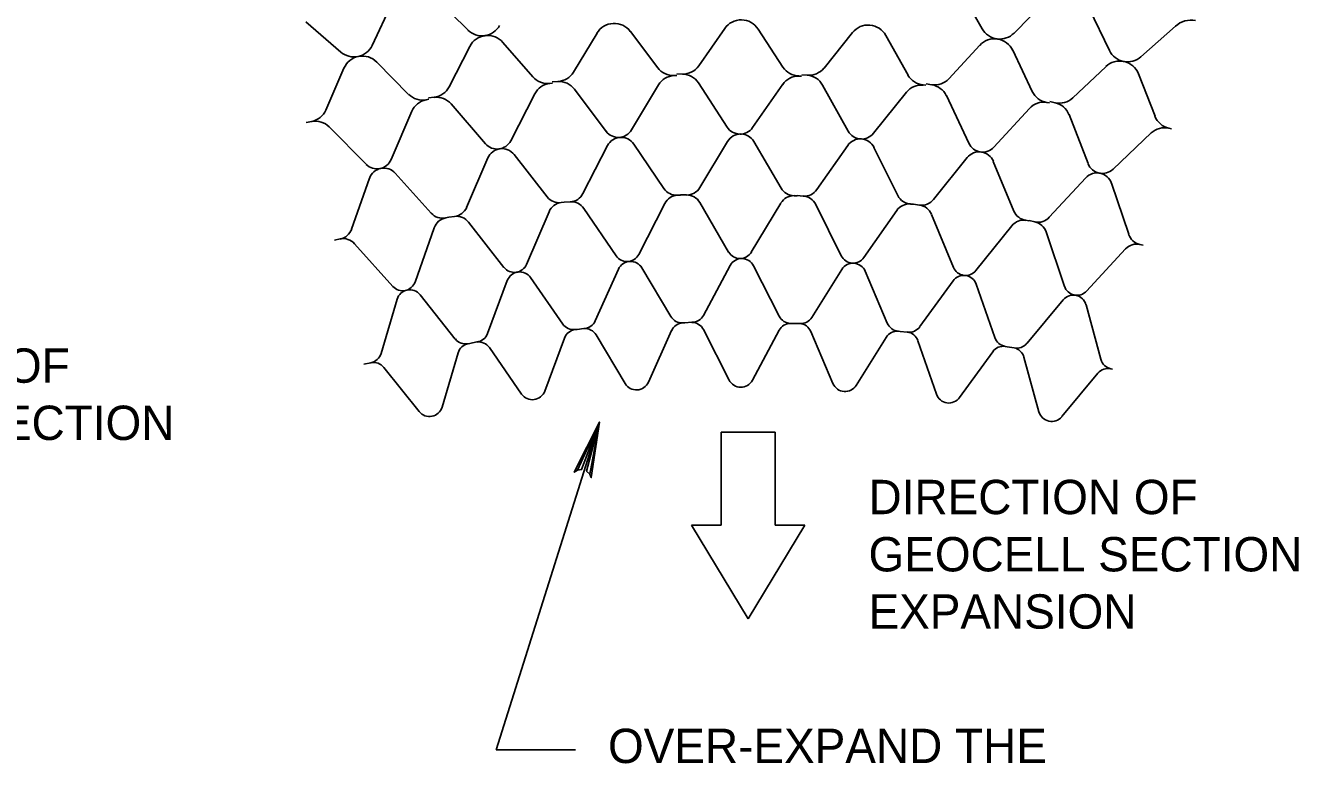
# Model space of a CAD drawing. Extents: x 638850 to 644908, y 297188 to 298900.
# Drawn here: x 639929 to 640040.3, y 297587.2 to 297651.7 of the extents above; entities that cross this region are included whole.
import ezdxf

# ---------------------------------------------------------------- set-up
doc = ezdxf.new("R2010")
doc.units = 0
for name, color, linetype in [('1', 7, 'Continuous'), ('5', 7, 'Continuous'), ('50', 7, 'Continuous'), ('9', 7, 'Continuous')]:
    doc.layers.add(name, color=color, linetype=linetype)

msp = doc.modelspace()

# ---------------------------------------------------------------- linework, layer by layer
at = {"layer": '1'}
for p, q in [((639970.17, 297588.39), (639979.19, 297617.04)), ((639994.53, 297616.16), (639989.82, 297616.16)), ((639989.82, 297616.16), (639989.82, 297608.04)), ((639994.53, 297608.04), (639994.53, 297616.16)), ((639989.82, 297608.04), (639987.22, 297608.04)), ((639987.22, 297608.04), (639992.17, 297599.84)), ((639992.17, 297599.84), (639997.13, 297608.04)), ((639997.13, 297608.04), (639994.53, 297608.04))]:
    msp.add_line(p, q, dxfattribs=at)
msp.add_lwpolyline([(639977.26, 297612.82), (639977.63, 297612.88), (639979.19, 297617.04), (639977.26, 297612.82), (639976.99, 297612.65), (639979.19, 297617.04), (639978.07, 297612.75), (639978.34, 297612.49), (639979.19, 297617.04), (639978.47, 297612.19), (639978.34, 297612.49)], dxfattribs=at)
at = {"layer": '5'}
for p, q in [((640010.63, 297654.9), (640012.63, 297651.38)), ((639964.82, 297654.14), (639967.69, 297651.29)), ((640015.42, 297651.01), (640018.26, 297653.89)), ((639959.33, 297649.94), (639961.05, 297653.61)), ((640021.98, 297653.15), (640023.74, 297649.5)), ((639953.53, 297652.01), (639956.59, 297649.36)), ((640026.49, 297648.94), (640029.53, 297651.63)), ((639976.93, 297647.6), (639978.98, 297651.01)), ((639981.89, 297651.16), (639984.28, 297647.98)), ((639987.86, 297648.15), (639990.14, 297651.41)), ((639993.06, 297651.37), (639995.22, 297648.03)), ((639998.81, 297647.96), (640001.3, 297651.06)), ((640004.21, 297650.81), (640006.15, 297647.34)), ((639966.05, 297646.31), (639967.87, 297649.85)), ((639970.76, 297650.2), (639973.36, 297647.19)), ((640009.72, 297647.03), (640012.42, 297649.95)), ((640015.3, 297649.51), (640017, 297645.91)), ((639959.73, 297648.48), (639962.52, 297645.66)), ((639955.29, 297644.29), (639956.86, 297647.94)), ((639985.72, 297647.31), (639985.95, 297647.32)), ((639985.95, 297647.44), (639986.45, 297647.43)), ((639996.61, 297647.26), (639996.85, 297647.26)), ((639996.86, 297647.38), (639997.35, 297647.34)), ((640020.54, 297645.35), (640023.43, 297648.08)), ((640026.28, 297647.45), (640027.73, 297643.75)), ((639974.84, 297646.62), (639975.08, 297646.64)), ((639975.07, 297646.76), (639975.56, 297646.79)), ((639977, 297646.11), (639979.77, 297642.43)), ((639981.98, 297642.55), (639984.35, 297646.49)), ((639987.84, 297646.66), (639990.35, 297642.8)), ((639992.56, 297642.77), (639995.2, 297646.54)), ((639998.69, 297646.47), (640000.93, 297642.45)), ((640007.48, 297646.48), (640007.72, 297646.46)), ((640007.73, 297646.58), (640008.22, 297646.5)), ((639964.04, 297645.19), (639964.28, 297645.23)), ((639964.26, 297645.35), (639964.75, 297645.41)), ((639966.23, 297644.83), (639969.24, 297641.35)), ((639971.44, 297641.61), (639973.54, 297645.71)), ((640003.14, 297642.27), (640006.02, 297645.85)), ((640009.5, 297645.55), (640011.46, 297641.39)), ((640018.27, 297644.96), (640018.5, 297644.92)), ((640018.53, 297645.04), (640019.01, 297644.93)), ((639960.99, 297639.96), (639962.8, 297644.19)), ((640013.65, 297641.05), (640016.77, 297644.43)), ((640020.22, 297643.89), (640021.89, 297639.61)), ((639953.57, 297643.2), (639954.05, 297643.29)), ((639955.57, 297642.82), (639958.81, 297639.55)), ((640028.93, 297642.71), (640029.16, 297642.66)), ((639987.96, 297637.52), (639990.39, 297641.55)), ((639992.69, 297641.53), (639995.06, 297637.48)), ((640024.06, 297639.12), (640027.4, 297642.29)), ((639971.73, 297640.4), (639974.63, 297636.71)), ((639977.75, 297637), (639979.89, 297641.18)), ((639982.19, 297641.32), (639984.83, 297637.44)), ((639998.19, 297637.35), (640000.88, 297641.2)), ((640003.17, 297641.03), (640005.26, 297636.82)), ((639967.59, 297635.79), (639969.45, 297640.11)), ((640008.38, 297636.48), (640011.33, 297640.14)), ((640013.6, 297639.81), (640015.4, 297635.47)), ((639957.54, 297633.9), (639959.1, 297638.33)), ((639961.35, 297638.78), (639964.5, 297635.28)), ((640018.49, 297634.92), (640021.68, 297638.37)), ((640023.93, 297637.89), (640025.43, 297633.44)), ((639975.85, 297636.21), (639976.12, 297636.24)), ((639976.12, 297636.25), (639976.64, 297636.28)), ((639982.62, 297631.67), (639984.91, 297636.13)), ((639986.02, 297636.86), (639986.28, 297636.87)), ((639986.28, 297636.88), (639986.81, 297636.88)), ((639987.95, 297636.21), (639990.48, 297631.89)), ((639992.46, 297631.87), (639995.05, 297636.17)), ((639996.2, 297636.81), (639996.47, 297636.81)), ((639996.47, 297636.82), (639996.99, 297636.78)), ((639998.09, 297636.04), (640000.32, 297631.55)), ((640006.36, 297636.08), (640006.63, 297636.06)), ((640006.63, 297636.07), (640007.15, 297635.99)), ((639965.75, 297634.87), (639966.02, 297634.92)), ((639966.02, 297634.93), (639966.53, 297635)), ((639972.81, 297630.8), (639974.8, 297635.41)), ((639977.83, 297635.7), (639980.64, 297631.55)), ((640002.29, 297631.41), (640005.17, 297635.51)), ((640008.19, 297635.18), (640010.11, 297630.55)), ((639963.09, 297629.27), (639964.75, 297634)), ((639967.76, 297634.49), (639970.85, 297630.55)), ((640012.07, 297630.27), (640015.22, 297634.18)), ((640016.45, 297634.66), (640016.71, 297634.62)), ((640016.72, 297634.63), (640017.23, 297634.52)), ((639956.03, 297632.93), (639956.54, 297633.03)), ((639957.8, 297632.61), (639961.15, 297628.89)), ((640018.21, 297633.64), (640019.82, 297628.89)), ((640021.75, 297628.48), (640025.15, 297632.16)), ((640026.41, 297632.56), (640026.68, 297632.5)), ((639978.83, 297625.88), (639980.85, 297630.39)), ((639982.89, 297630.51), (639985.42, 297626.26)), ((639988.29, 297626.35), (639990.61, 297630.71)), ((639992.65, 297630.69), (639994.89, 297626.29)), ((639997.75, 297626.18), (640000.37, 297630.37)), ((639969.42, 297624.77), (639971.14, 297629.4)), ((639973.16, 297629.66), (639975.98, 297625.6)), ((640002.41, 297630.21), (640004.34, 297625.67)), ((640007.19, 297625.37), (640010.08, 297629.37)), ((639963.52, 297628.16), (639966.6, 297624.29)), ((640012.1, 297629.08), (640013.73, 297624.41)), ((639960.12, 297623.02), (639961.51, 297627.76)), ((640016.55, 297623.92), (640019.71, 297627.72)), ((640021.7, 297627.28), (640023, 297622.52)), ((639977.07, 297625.11), (639977.23, 297625.13)), ((639977.23, 297625.13), (639977.84, 297625.21)), ((639985.5, 297625.03), (639983.47, 297620.52)), ((639986.48, 297625.71), (639986.64, 297625.71)), ((639986.64, 297625.71), (639987.26, 297625.75)), ((639990.51, 297620.71), (639988.27, 297625.12)), ((639994.88, 297625.05), (639992.55, 297620.69)), ((639995.91, 297625.66), (639996.07, 297625.66)), ((639996.07, 297625.66), (639996.69, 297625.64)), ((639999.59, 297620.4), (639997.66, 297624.95)), ((640005.31, 297624.97), (640005.47, 297624.96)), ((640005.47, 297624.96), (640006.09, 297624.9)), ((639967.72, 297623.88), (639967.88, 297623.91)), ((639967.88, 297623.91), (639968.49, 297624.03)), ((639976.13, 297624.37), (639974.42, 297619.74)), ((639981.43, 297620.4), (639978.9, 297624.65)), ((640004.24, 297624.43), (640001.63, 297620.24)), ((640008.63, 297619.48), (640007.01, 297624.14)), ((639966.84, 297623.08), (639965.44, 297618.34)), ((639972.39, 297619.48), (639969.58, 297623.54)), ((640013.55, 297623.18), (640010.65, 297619.18)), ((640014.65, 297623.65), (640014.8, 297623.62)), ((640014.8, 297623.62), (640015.42, 297623.53)), ((640017.58, 297617.94), (640016.28, 297622.71)), ((639958.62, 297622.1), (639959.23, 297622.22)), ((639963.44, 297617.95), (639960.35, 297621.81)), ((640023.87, 297621.69), (640024.02, 297621.66)), ((640022.74, 297621.31), (640019.58, 297617.51))]:
    msp.add_line(p, q, dxfattribs=at)
for centre, radius, start, end in [((639968.93, 297652.53), 1.76, 225.1464, 330.9779), ((639980.48, 297650.1), 1.76, 36.9087, 148.9868), ((639991.58, 297650.41), 1.76, 33.0183, 145.0964), ((640002.67, 297649.96), 1.76, 29.1279, 141.206), ((640030.87, 297650.11), 2.03, 78.6103, 131.5261), ((639969.43, 297649.05), 1.76, 40.7991, 152.8772), ((640013.71, 297648.75), 1.76, 25.2376, 137.3157), ((640014.16, 297652.25), 1.76, 209.5849, 315.4164), ((639957.74, 297650.69), 1.76, 229.0368, 334.8683), ((640025.33, 297650.26), 1.76, 205.6945, 311.5261), ((639958.48, 297647.25), 1.76, 44.6895, 156.7676), ((639986.48, 297649.12), 1.69, 269.0574, 325.0964), ((640024.64, 297646.81), 1.76, 21.3472, 133.4253), ((639974.64, 297648.3), 1.69, 220.7991, 276.8381), ((639975.48, 297648.48), 1.69, 272.9478, 328.9868), ((639985.63, 297649), 1.69, 216.9087, 272.9477), ((639985.81, 297645.62), 1.69, 92.9478, 148.9868), ((639986.42, 297645.74), 1.69, 33.0183, 89.0574), ((639996.59, 297645.57), 1.69, 89.0574, 145.0964), ((639996.64, 297648.96), 1.69, 213.0183, 269.0574), ((639997.49, 297649.02), 1.69, 265.167, 321.206), ((639997.21, 297645.65), 1.69, 29.1279, 85.167), ((640007.62, 297648.17), 1.69, 209.1279, 265.167), ((639964.55, 297647.09), 1.69, 276.8381, 332.8772), ((639975.05, 297644.94), 1.69, 96.8381, 152.8772), ((639975.65, 297645.1), 1.69, 36.9087, 92.9477), ((640007.34, 297644.79), 1.69, 85.167, 141.206), ((640008.48, 297648.17), 1.69, 261.2766, 317.3157), ((640007.96, 297644.83), 1.69, 25.2376, 81.2766), ((639963.73, 297646.85), 1.69, 224.6895, 280.7285), ((639964.36, 297643.52), 1.69, 100.7285, 156.7676), ((639964.95, 297643.72), 1.69, 40.7991, 96.8381), ((640018.01, 297643.29), 1.69, 81.2766, 137.3157), ((640018.53, 297646.63), 1.69, 205.2376, 261.2766), ((640019.38, 297646.58), 1.69, 257.3862, 313.4253), ((640018.64, 297643.28), 1.69, 21.3472, 77.3862), ((639953.74, 297644.96), 1.69, 280.7285, 336.7676), ((640029.3, 297644.36), 1.69, 201.3472, 257.3862), ((639954.37, 297641.63), 1.69, 44.6895, 100.7285), ((639991.47, 297643.53), 1.34, 213.0183, 325.0964), ((640028.56, 297641.06), 1.69, 77.3862, 133.4253), ((639970.25, 297642.22), 1.34, 220.7991, 332.8772), ((639980.84, 297643.24), 1.34, 216.9087, 328.9868), ((639981.08, 297640.57), 1.34, 34.2045, 152.818), ((639991.53, 297640.86), 1.34, 30.3142, 148.9276), ((640001.98, 297640.43), 1.34, 26.4238, 145.0373), ((640002.09, 297643.1), 1.34, 209.1279, 321.206), ((639970.68, 297639.58), 1.34, 38.0949, 156.7084), ((640012.37, 297639.3), 1.34, 22.5334, 141.1469), ((640012.67, 297641.96), 1.34, 205.2376, 317.3157), ((639959.76, 297640.49), 1.34, 224.6895, 336.7676), ((640023.14, 297640.09), 1.34, 201.3472, 313.4253), ((639960.36, 297637.88), 1.34, 41.9853, 160.5988), ((640022.66, 297637.46), 1.34, 18.643, 137.2565), ((639985.93, 297638.19), 1.34, 214.2045, 273.5113), ((639986.82, 297638.21), 1.34, 269.6209, 328.9276), ((639996.21, 297638.15), 1.34, 210.3142, 269.6209), ((639997.09, 297638.11), 1.34, 265.7305, 325.0373), ((639975.68, 297637.53), 1.34, 218.0949, 277.4017), ((639976.02, 297634.88), 1.34, 97.4017, 156.7084), ((639976.56, 297637.61), 1.34, 273.5113, 332.818), ((639976.72, 297634.95), 1.34, 34.2045, 93.5113), ((639986.1, 297635.52), 1.34, 93.5113, 152.818), ((639986.8, 297635.54), 1.34, 30.3142, 89.6209), ((639996.19, 297635.48), 1.34, 89.6209, 148.9276), ((639996.89, 297635.45), 1.34, 26.4238, 85.7305), ((640006.26, 297634.75), 1.34, 85.7305, 145.0373), ((640006.46, 297637.41), 1.34, 206.4238, 265.7305), ((640007.34, 297637.32), 1.34, 261.8401, 321.1469), ((640006.96, 297634.67), 1.34, 22.5334, 81.8401), ((639965.49, 297636.18), 1.34, 221.9853, 281.292), ((639966.02, 297633.56), 1.34, 101.292, 160.5988), ((639966.36, 297636.32), 1.34, 277.4017, 336.7084), ((639966.71, 297633.67), 1.34, 38.0949, 97.4017), ((640016.64, 297635.98), 1.34, 202.5334, 261.8401), ((640017.51, 297635.83), 1.34, 257.9498, 317.2565), ((639956.28, 297634.34), 1.34, 281.292, 340.5988), ((640016.26, 297633.34), 1.34, 81.8401, 141.1469), ((640016.95, 297633.21), 1.34, 18.643, 77.9498), ((639956.8, 297631.72), 1.34, 41.9853, 101.292), ((640026.14, 297631.25), 1.34, 77.9498, 137.2565), ((640026.69, 297633.87), 1.34, 198.643, 257.9498), ((639981.6, 297632.2), 1.15, 214.2045, 332.818), ((639991.48, 297632.47), 1.15, 210.3142, 328.9276), ((640001.35, 297632.07), 1.15, 206.4238, 325.0373), ((639971.76, 297631.26), 1.15, 218.0949, 336.7084), ((639981.9, 297629.92), 1.15, 30.8329, 155.7938), ((639991.63, 297630.17), 1.15, 26.9426, 151.9034), ((640001.35, 297629.76), 1.15, 23.0522, 148.013), ((640011.18, 297630.99), 1.15, 202.5334, 321.1469), ((639962, 297629.66), 1.15, 221.9853, 340.5988), ((639972.22, 297629), 1.15, 34.7233, 159.6841), ((640011.02, 297628.7), 1.15, 19.1618, 144.1226), ((639962.62, 297627.44), 1.15, 38.6137, 163.5745), ((640020.59, 297626.98), 1.15, 15.2714, 140.2323), ((640020.91, 297629.26), 1.15, 198.643, 317.2565), ((639986.41, 297626.85), 1.15, 210.8329, 273.3134), ((639987.27, 297626.9), 1.15, 269.423, 331.9034), ((639995.92, 297626.81), 1.15, 206.9426, 269.423), ((639996.78, 297626.79), 1.15, 265.5326, 328.013), ((639976.92, 297626.26), 1.15, 214.7233, 277.2037), ((639977.21, 297623.97), 1.15, 97.2037, 159.6841), ((639977.78, 297626.35), 1.15, 273.3133, 335.7938), ((639977.91, 297624.06), 1.15, 30.8329, 93.3133), ((639986.55, 297624.56), 1.15, 93.3133, 155.7938), ((639987.25, 297624.59), 1.15, 26.9426, 89.423), ((639995.9, 297624.51), 1.15, 89.423, 151.9034), ((639996.6, 297624.5), 1.15, 23.0522, 85.5326), ((640005.22, 297623.82), 1.15, 85.5326, 148.013), ((640005.4, 297626.12), 1.15, 203.0522, 265.5326), ((640006.26, 297626.04), 1.15, 261.6422, 324.1226), ((640005.92, 297623.77), 1.15, 19.1618, 81.6422), ((639967.5, 297625.01), 1.15, 218.6137, 281.0941), ((639967.94, 297622.75), 1.15, 101.0941, 163.5745), ((639968.34, 297625.17), 1.15, 277.2037, 339.6841), ((639968.63, 297622.89), 1.15, 34.7233, 97.2037), ((640014.81, 297624.79), 1.15, 199.1618, 261.6422), ((640015.66, 297624.65), 1.15, 257.7518, 320.2323), ((639959.01, 297623.35), 1.15, 281.0941, 343.5745), ((640014.48, 297622.51), 1.15, 81.6422, 144.1226), ((640015.17, 297622.4), 1.15, 15.2714, 77.7518), ((639959.46, 297621.09), 1.15, 38.6137, 101.0941), ((640023.63, 297620.57), 1.15, 77.7518, 140.2323), ((640024.11, 297622.82), 1.15, 195.2714, 257.7518), ((639982.42, 297620.99), 1.15, 210.8329, 335.7938), ((639991.54, 297621.23), 1.15, 206.9426, 331.9034), ((640000.65, 297620.85), 1.15, 203.0522, 328.013), ((639973.34, 297620.14), 1.15, 214.7233, 339.6841), ((640009.72, 297619.85), 1.15, 199.1618, 324.1226), ((639964.34, 297618.67), 1.15, 218.6137, 343.5745), ((640018.7, 297618.24), 1.15, 195.2714, 320.2323)]:
    msp.add_arc(centre, radius, start, end, dxfattribs=at)
at = {"layer": '50'}
for p, q in [((639978.83, 297625.88), (639980.85, 297630.39)), ((639982.89, 297630.51), (639985.42, 297626.26)), ((639988.29, 297626.35), (639990.61, 297630.71)), ((639992.65, 297630.69), (639994.89, 297626.29)), ((639997.75, 297626.18), (640000.37, 297630.37)), ((639969.42, 297624.77), (639971.14, 297629.4)), ((639973.16, 297629.66), (639975.98, 297625.6)), ((640002.41, 297630.21), (640004.34, 297625.67)), ((640007.19, 297625.37), (640010.08, 297629.37)), ((639963.52, 297628.16), (639966.6, 297624.29)), ((640012.1, 297629.08), (640013.73, 297624.41)), ((639960.12, 297623.02), (639961.51, 297627.76)), ((640016.55, 297623.92), (640019.71, 297627.72)), ((640021.7, 297627.28), (640023, 297622.52)), ((639985.5, 297625.03), (639983.47, 297620.52)), ((639990.51, 297620.71), (639988.27, 297625.12)), ((639994.88, 297625.05), (639992.55, 297620.69)), ((639999.59, 297620.4), (639997.66, 297624.95)), ((639976.13, 297624.37), (639974.42, 297619.74)), ((639981.43, 297620.4), (639978.9, 297624.65)), ((640004.24, 297624.43), (640001.63, 297620.24)), ((640008.63, 297619.48), (640007.01, 297624.14)), ((639966.84, 297623.08), (639965.44, 297618.34)), ((639972.39, 297619.48), (639969.58, 297623.54)), ((640013.55, 297623.18), (640010.65, 297619.18)), ((640017.58, 297617.94), (640016.28, 297622.71)), ((639963.44, 297617.95), (639960.35, 297621.81)), ((640022.74, 297621.31), (640019.58, 297617.51))]:
    msp.add_line(p, q, dxfattribs=at)
for centre, start, end in [((639981.9, 297629.92), 30.8329, 155.7938), ((639991.63, 297630.17), 26.9426, 151.9034), ((640001.35, 297629.76), 23.0522, 148.013), ((639972.22, 297629), 34.7233, 159.6841), ((640011.02, 297628.7), 19.1618, 144.1226), ((639962.62, 297627.44), 38.6137, 163.5745), ((640020.59, 297626.98), 15.2714, 140.2323), ((639986.41, 297626.85), 210.8329, 273.3134), ((639987.27, 297626.9), 269.423, 331.9034), ((639995.92, 297626.81), 206.9426, 269.423), ((639996.78, 297626.79), 265.5326, 328.013), ((639976.92, 297626.26), 214.7233, 277.2037), ((639977.21, 297623.97), 97.2037, 159.6841), ((639977.78, 297626.35), 273.3133, 335.7938), ((639977.91, 297624.06), 30.8329, 93.3133), ((639986.55, 297624.56), 93.3133, 155.7938), ((639987.25, 297624.59), 26.9426, 89.423), ((639995.9, 297624.51), 89.423, 151.9034), ((639996.6, 297624.5), 23.0522, 85.5326), ((640005.22, 297623.82), 85.5326, 148.013), ((640005.4, 297626.12), 203.0522, 265.5326), ((640006.26, 297626.04), 261.6422, 324.1226), ((640005.92, 297623.77), 19.1618, 81.6422), ((639967.5, 297625.01), 218.6137, 281.0941), ((639967.94, 297622.75), 101.0941, 163.5745), ((639968.34, 297625.17), 277.2037, 339.6841), ((639968.63, 297622.89), 34.7233, 97.2037), ((640014.81, 297624.79), 199.1618, 261.6422), ((640015.66, 297624.65), 257.7518, 320.2323), ((639959.01, 297623.35), 281.0941, 343.5745), ((640014.48, 297622.51), 81.6422, 144.1226), ((640015.17, 297622.4), 15.2714, 77.7518), ((639959.46, 297621.09), 38.6137, 101.0941), ((640023.63, 297620.57), 77.7518, 140.2323), ((640024.11, 297622.82), 195.2714, 257.7518), ((639982.42, 297620.99), 210.8329, 335.7938), ((639991.54, 297621.23), 206.9426, 331.9034), ((640000.65, 297620.85), 203.0522, 328.013), ((639973.34, 297620.14), 214.7233, 339.6841), ((640009.72, 297619.85), 199.1618, 324.1226), ((639964.34, 297618.67), 218.6137, 343.5745), ((640018.7, 297618.24), 195.2714, 320.2323)]:
    msp.add_arc(centre, 1.15, start, end, dxfattribs=at)
at = {"layer": '9'}
msp.add_line((639970.17, 297588.39), (639977.11, 297588.39), dxfattribs=at)

# ---------------------------------------------------------------- texts
at = {"layer": '1'}
for s, p in [('DIRECTION OF', (639904.16, 297620.47)), ('GEOCELL SECTION', (639904.16, 297615.47)), ('DIRECTION OF', (640002.7, 297608.99)), ('GEOCELL SECTION', (640002.7, 297603.99)), ('EXPANSION', (640002.7, 297598.99)), ('OVER-EXPAND THE', (639979.94, 297587.25))]:
    msp.add_text(s, height=3, dxfattribs=at).set_placement(p)

doc.saveas('drawing.dxf')
